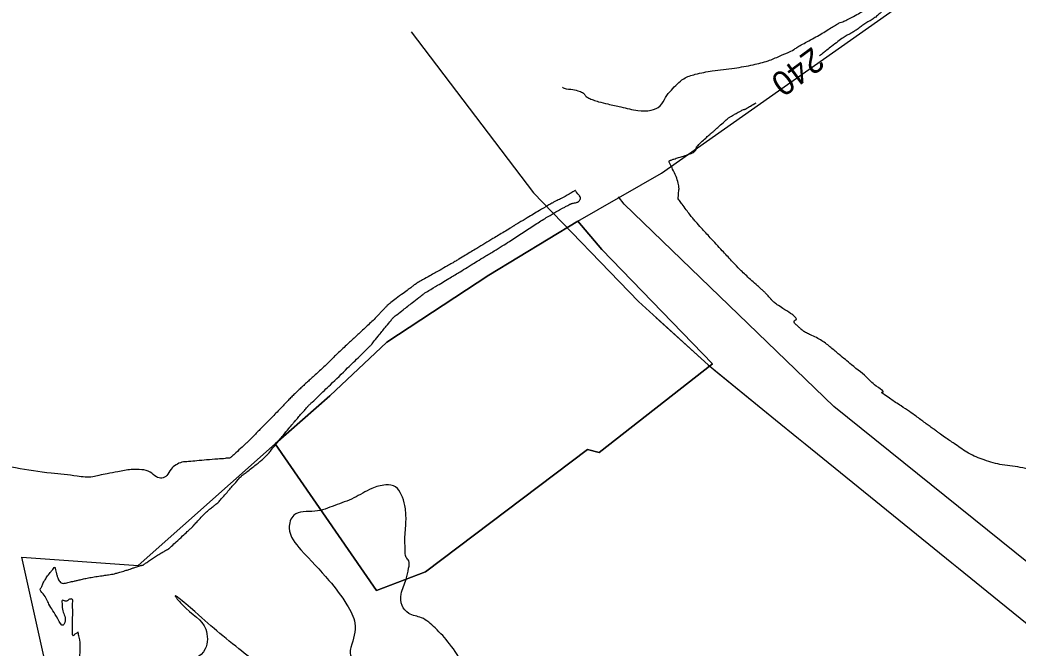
# Model space of a CAD drawing. Extents: x -478464 to -472469, y -1120963 to -1113785.
# Drawn here: x -477139.2 to -476975, y -1115096.3 to -1114993 of the extents above; entities that cross this region are included whole.
import ezdxf

# ---------------------------------------------------------------- set-up
doc = ezdxf.new("R2010")
doc.units = 0
for name, color, linetype in [('ObPÚ', 7, 'Continuous'), ('silnice', 7, 'Continuous'), ('telekomunikační kabel_O2', 7, 'Continuous'), ('Vrstevnice_hlavni', 7, 'Continuous'), ('Vrstevnice_popis', 7, 'Continuous'), ('Vrstevnice_vedlejsi', 7, 'Continuous')]:
    doc.layers.add(name, color=color, linetype=linetype)

msp = doc.modelspace()

# ---------------------------------------------------------------- linework, layer by layer
at = {"layer": 'ObPÚ'}
for p, q in [((-477047.46, -1115026.08), (-477062.09, -1115034.97)), ((-477043.48, -1115030.71), (-477047.46, -1115026.08)), ((-477072.47, -1115083.76), (-477045.85, -1115063.61))]:
    msp.add_line(p, q, dxfattribs=at)
for points in [[(-477231.42, -1115250.62), (-477154.22, -1115173.58), (-477134.18, -1115148.75), (-477133.16, -1115130.26), (-477132.09, -1115111.94), (-477138.91, -1115081.32), (-477119.74, -1115082.72), (-477097.23, -1115062.71), (-477080.55, -1115086.81), (-477072.47, -1115083.76), (-477045.85, -1115063.61), (-477043.93, -1115064.09), (-477025.31, -1115049.55), (-477043.48, -1115030.71), (-477047.46, -1115026.08), (-477033.7, -1115018.17), (-476933.96, -1114947.92), (-476834.35, -1114877.76), (-476714.64, -1114803.8), (-476602.93, -1114745.91), (-476491.34, -1114705.52)], [(-477047.46, -1115026.08), (-477043.48, -1115030.71), (-477025.31, -1115049.55), (-477043.93, -1115064.09), (-477045.85, -1115063.61), (-477072.47, -1115083.76), (-477080.55, -1115086.81), (-477097.23, -1115062.71), (-477088.23, -1115054.79), (-477078.85, -1115045.98), (-477062.09, -1115034.97), (-477047.46, -1115026.08)], [(-477045.85, -1115063.61), (-477043.93, -1115064.09), (-477025.31, -1115049.55), (-477043.48, -1115030.71)], [(-477062.09, -1115034.97), (-477078.85, -1115045.98), (-477088.23, -1115054.79), (-477097.23, -1115062.71), (-477080.55, -1115086.81), (-477072.47, -1115083.76)]]:
    msp.add_lwpolyline(points, dxfattribs=at)
at = {"layer": 'silnice'}
msp.add_lwpolyline([(-476200.543, -1116268.153), (-476239.965, -1116179.199), (-476260.934, -1116109.546), (-476288.613, -1116007.164), (-476289.451, -1115970.24), (-476274.354, -1115930.798), (-476261.922, -1115907.288), (-476366.595, -1115823.727), (-476390.845, -1115803.24), (-476425.665, -1115718.481), (-476494.983, -1115557.356), (-476524.795, -1115496.42), (-476580.823, -1115418.032), (-476641.911, -1115352.297), (-476741.891, -1115268.259), (-476824.194, -1115202.313), (-477005.33, -1115056.573), (-477039.82, -1115023.276), (-477040.729, -1115022.048)], dxfattribs=at)
at = {"layer": 'telekomunikační kabel_O2'}
for p, q in [((-477011.16, -1115061.79), (-477010.07, -1115062.67)), ((-477011.16, -1115061.79), (-477010.07, -1115062.67)), ((-476985.91, -1115082.25), (-476984.82, -1115083.13)), ((-476985.91, -1115082.25), (-476984.82, -1115083.13))]:
    msp.add_line(p, q, dxfattribs=at)
for points in [[(-477074.85, -1114994.92), (-477054.75, -1115021.38), (-477037.48, -1115039.27), (-477026.01, -1115049.69), (-477014.91, -1115058.73)], [(-477034.596, -1115041.89), (-477026.01, -1115049.69), (-477014.91, -1115058.73)], [(-477025.002, -1115050.511), (-477014.91, -1115058.73)], [(-477025.002, -1115050.511), (-477014.91, -1115058.73)], [(-477014.91, -1115058.73), (-477011.16, -1115061.79)], [(-477014.91, -1115058.73), (-477011.16, -1115061.79)], [(-477014.91, -1115058.73), (-477014.596, -1115058.986)], [(-477014.91, -1115058.73), (-477014.596, -1115058.986)], [(-477010.07, -1115062.67), (-476985.91, -1115082.25)], [(-476984.82, -1115083.13), (-476978.14, -1115088.55), (-476938.13, -1115120.98)]]:
    msp.add_lwpolyline(points, dxfattribs=at)
at = {"layer": 'Vrstevnice_hlavni'}
for points in [[(-477049.979, -1115004.029), (-477049.673, -1115004.193), (-477048.26, -1115004.404), (-477047.204, -1115004.683), (-477046.505, -1115005.027), (-477046.164, -1115005.438), (-477045.639, -1115005.805), (-477044.929, -1115006.127), (-477044.034, -1115006.405), (-477042.508, -1115006.787), (-477040.351, -1115007.273), (-477037.562, -1115007.863), (-477035.407, -1115007.799), (-477033.886, -1115007.079), (-477033, -1115005.704), (-477032.062, -1115004.503), (-477031.073, -1115003.477), (-477030.034, -1115002.625), (-477028.119, -1115001.907), (-477025.328, -1115001.324), (-477021.663, -1115000.876), (-477018.599, -1115000.325), (-477016.138, -1114999.672), (-477014.278, -1114998.917), (-477012.873, -1114998.304), (-477011.923, -1114997.835), (-477011.428, -1114997.509), (-477010.705, -1114997.08), (-477009.754, -1114996.549), (-477008.574, -1114995.914), (-477007.491, -1114995.299), (-477006.505, -1114994.702), (-477005.616, -1114994.125), (-477004.874, -1114993.69), (-477004.28, -1114993.398), (-477003.833, -1114993.249), (-477003.188, -1114992.955), (-477002.345, -1114992.516), (-477001.305, -1114991.933), (-477000.403, -1114991.481), (-476999.64, -1114991.162), (-476999.016, -1114990.973), (-476998.464, -1114990.728), (-476997.985, -1114990.425), (-476997.579, -1114990.066), (-476997.143, -1114989.765), (-476996.676, -1114989.524), (-476996.178, -1114989.342), (-476995.627, -1114989.011), (-476995.023, -1114988.533), (-476994.365, -1114987.907), (-476993.741, -1114987.384), (-476993.153, -1114986.963), (-476992.599, -1114986.645), (-476992.009, -1114986.355), (-476991.383, -1114986.092), (-476990.719, -1114985.856), (-476990.255, -1114985.689), (-476989.991, -1114985.591), (-476989.925, -1114985.561), (-476989.901, -1114985.553), (-476989.919, -1114985.568), (-476989.977, -1114985.605), (-476990.02, -1114985.633), (-476990.048, -1114985.653), (-476990.061, -1114985.663), (-476990.326, -1114985.857), (-476990.841, -1114986.233), (-476991.608, -1114986.792), (-476992.308, -1114987.388), (-476992.94, -1114988.02), (-476993.504, -1114988.689), (-476994.025, -1114989.245), (-476994.503, -1114989.688), (-476994.937, -1114990.017), (-476995.402, -1114990.301), (-476995.899, -1114990.54), (-476996.428, -1114990.734), (-476996.92, -1114991.026), (-476997.375, -1114991.417), (-476997.795, -1114991.906), (-476998.298, -1114992.365), (-476998.884, -1114992.793), (-476999.553, -1114993.19), (-477000.214, -1114993.61), (-477000.867, -1114994.052), (-477001.512, -1114994.518), (-477002.106, -1114994.907), (-477002.649, -1114995.22), (-477003.142, -1114995.458), (-477003.814, -1114995.885), (-477004.665, -1114996.502)], [(-477004.665, -1114996.502), (-477005.695, -1114997.309), (-477006.489, -1114997.933), (-477007.047, -1114998.372), (-477007.691, -1114998.882)], [(-477017.894, -1115036.673), (-477018.831, -1115035.848), (-477019.673, -1115035.079), (-477020.422, -1115034.367), (-477021.076, -1115033.712), (-477022.168, -1115032.564), (-477023.697, -1115030.923), (-477025.662, -1115028.788), (-477027.122, -1115027.188), (-477028.074, -1115026.123), (-477028.52, -1115025.593), (-477029.034, -1115024.943), (-477029.617, -1115024.173), (-477030.269, -1115023.282), (-477030.708, -1115022.682), (-477030.934, -1115022.374), (-477030.946, -1115022.357), (-477030.928, -1115022.077), (-477030.878, -1115021.535), (-477030.797, -1115020.729), (-477030.934, -1115019.788), (-477031.286, -1115018.713), (-477031.856, -1115017.503), (-477032.238, -1115016.683), (-477032.433, -1115016.253), (-477032.44, -1115016.214), (-477032.443, -1115016.185), (-477032.441, -1115016.166), (-477032.435, -1115016.159), (-477032.431, -1115016.153), (-477032.428, -1115016.149), (-477032.426, -1115016.147), (-477032.373, -1115016.122), (-477032.267, -1115016.074), (-477032.11, -1115016.003), (-477031.64, -1115015.843), (-477030.858, -1115015.596), (-477029.763, -1115015.26), (-477028.959, -1115014.975), (-477028.444, -1115014.74), (-477028.219, -1115014.556), (-477028.06, -1115014.364), (-477027.968, -1115014.165), (-477027.943, -1115013.958), (-477027.674, -1115013.593), (-477027.161, -1115013.071), (-477026.405, -1115012.392), (-477025.889, -1115011.927), (-477025.616, -1115011.677), (-477025.583, -1115011.642), (-477025.534, -1115011.602), (-477025.469, -1115011.556), (-477025.387, -1115011.505), (-477025.033, -1115011.201), (-477024.407, -1115010.643), (-477023.509, -1115009.833), (-477022.858, -1115009.263), (-477022.455, -1115008.935), (-477022.299, -1115008.848), (-477021.991, -1115008.674), (-477021.533, -1115008.413), (-477020.923, -1115008.064), (-477020.468, -1115007.826), (-477020.167, -1115007.697), (-477020.021, -1115007.678), (-477019.883, -1115007.635), (-477019.754, -1115007.567), (-477019.633, -1115007.475), (-477019.398, -1115007.325), (-477019.047, -1115007.117), (-477018.115, -1115006.584)], [(-476873.251, -1115143.677), (-476873.507, -1115142.01), (-476873.554, -1115139.102), (-476873.522, -1115134.12), (-476873.41, -1115127.063), (-476873.808, -1115122.086), (-476874.717, -1115119.19), (-476876.136, -1115118.374), (-476877.354, -1115117.171), (-476878.371, -1115115.579), (-476879.185, -1115113.6), (-476882.364, -1115111.475), (-476887.908, -1115109.205), (-476895.815, -1115106.789), (-476902.242, -1115103.761), (-476907.186, -1115100.12), (-476910.649, -1115095.867), (-476913.66, -1115091.883), (-476916.218, -1115088.167), (-476918.324, -1115084.72), (-476919.725, -1115082.379), (-476920.421, -1115081.145), (-476920.412, -1115081.017), (-476920.426, -1115080.932), (-476920.462, -1115080.891), (-476920.521, -1115080.893), (-476920.576, -1115080.895), (-476920.627, -1115080.896), (-476920.674, -1115080.898), (-476921.736, -1115080.799), (-476923.814, -1115080.599), (-476926.907, -1115080.3), (-476932.302, -1115079.591), (-476940, -1115078.472), (-476950, -1115076.944), (-476957.876, -1115075.006), (-476963.629, -1115072.657), (-476967.259, -1115069.897), (-476970.802, -1115067.892), (-476974.259, -1115066.643), (-476977.631, -1115066.149), (-476980.601, -1115065.341), (-476983.17, -1115064.218), (-476985.338, -1115062.781), (-476986.878, -1115061.747), (-476987.79, -1115061.118), (-476988.074, -1115060.892), (-476988.478, -1115060.587), (-476989.003, -1115060.204), (-476989.648, -1115059.743), (-476990.332, -1115059.246), (-476991.055, -1115058.714), (-476991.817, -1115058.146), (-476992.891, -1115057.395), (-476994.277, -1115056.46), (-476995.976, -1115055.343), (-476997.039, -1115054.593), (-476997.464, -1115054.21), (-476997.254, -1115054.195), (-476998.009, -1115053.437), (-476999.729, -1115051.937), (-477002.416, -1115049.693), (-477004.444, -1115048.001), (-477005.814, -1115046.86), (-477006.527, -1115046.27), (-477007.324, -1115045.723), (-477008.206, -1115045.221), (-477009.173, -1115044.763), (-477009.833, -1115044.445), (-477010.186, -1115044.267), (-477010.232, -1115044.228), (-477010.318, -1115044.158), (-477010.443, -1115044.058), (-477010.608, -1115043.927), (-477010.866, -1115043.703), (-477011.219, -1115043.389), (-477011.666, -1115042.982), (-477011.859, -1115042.654), (-477011.796, -1115042.405), (-477011.479, -1115042.235), (-477011.695, -1115041.846), (-477012.445, -1115041.236), (-477013.729, -1115040.407), (-477014.642, -1115039.799), (-477015.184, -1115039.41), (-477015.355, -1115039.241), (-477015.476, -1115039.117), (-477015.545, -1115039.038), (-477015.564, -1115039.003), (-477015.672, -1115038.875), (-477015.869, -1115038.653), (-477016.157, -1115038.339), (-477016.405, -1115038.07), (-477016.615, -1115037.849), (-477016.786, -1115037.674), (-477017.213, -1115037.282), (-477017.894, -1115036.673)]]:
    msp.add_spline(points, degree=3, dxfattribs=at)
at = {"layer": 'Vrstevnice_vedlejsi'}
for points in [[(-477108.024, -1115073.453), (-477107.41, -1115072.982), (-477106.961, -1115072.629), (-477106.676, -1115072.395), (-477106.556, -1115072.278), (-477106.091, -1115071.757), (-477105.281, -1115070.832), (-477104.126, -1115069.502), (-477103.309, -1115068.574), (-477102.828, -1115068.046), (-477102.685, -1115067.92), (-477102.316, -1115067.626), (-477101.72, -1115067.165), (-477100.898, -1115066.537), (-477100.184, -1115065.97), (-477099.579, -1115065.464), (-477099.081, -1115065.02), (-477098.73, -1115064.701), (-477098.524, -1115064.509), (-477098.465, -1115064.444), (-477098.01, -1115063.889), (-477097.162, -1115062.844), (-477095.919, -1115061.311), (-477094.978, -1115060.158), (-477094.339, -1115059.385), (-477094.002, -1115058.992), (-477093.57, -1115058.494), (-477093.044, -1115057.889), (-477092.423, -1115057.178), (-477091.967, -1115056.663), (-477091.675, -1115056.343), (-477091.547, -1115056.218), (-477091.414, -1115056.093), (-477091.276, -1115055.968), (-477091.133, -1115055.843), (-477090.09, -1115054.841), (-477088.145, -1115052.963), (-477085.299, -1115050.207), (-477083.328, -1115048.299), (-477082.232, -1115047.238), (-477082.012, -1115047.025), (-477081.803, -1115046.81), (-477081.606, -1115046.593), (-477081.422, -1115046.376), (-477080.916, -1115045.76), (-477080.09, -1115044.745), (-477078.942, -1115043.332), (-477078.165, -1115042.381), (-477077.759, -1115041.889), (-477077.722, -1115041.859), (-477077.193, -1115041.444), (-477076.171, -1115040.644), (-477074.656, -1115039.459), (-477073.586, -1115038.623), (-477072.96, -1115038.136), (-477072.779, -1115037.999), (-477071.961, -1115037.49), (-477070.508, -1115036.61), (-477068.419, -1115035.359), (-477066.799, -1115034.381), (-477065.649, -1115033.675), (-477064.968, -1115033.243), (-477064.004, -1115032.647), (-477062.756, -1115031.889), (-477061.226, -1115030.967), (-477059.874, -1115030.136), (-477058.7, -1115029.396), (-477057.706, -1115028.747), (-477056.705, -1115028.092), (-477055.698, -1115027.432), (-477054.685, -1115026.767), (-477053.73, -1115026.157), (-477052.836, -1115025.601), (-477052, -1115025.101), (-477051.326, -1115024.7), (-477050.814, -1115024.399), (-477050.463, -1115024.197), (-477050.058, -1115023.975), (-477049.6, -1115023.733), (-477049.089, -1115023.47), (-477048.739, -1115023.29), (-477048.551, -1115023.192), (-477048.525, -1115023.177), (-477048.392, -1115023.144), (-477048.151, -1115023.091), (-477047.802, -1115023.02), (-477047.557, -1115022.962), (-477047.416, -1115022.917), (-477047.38, -1115022.886), (-477047.304, -1115022.801), (-477047.188, -1115022.663), (-477047.034, -1115022.472), (-477047.024, -1115022.224), (-477047.159, -1115021.92), (-477047.44, -1115021.559), (-477047.642, -1115021.3), (-477047.764, -1115021.143)], [(-477047.764, -1115021.143), (-477047.807, -1115021.087), (-477047.84, -1115021.051), (-477047.862, -1115021.035), (-477047.874, -1115021.038), (-477048.066, -1115021.148), (-477048.439, -1115021.365), (-477048.993, -1115021.689), (-477049.369, -1115021.906), (-477049.566, -1115022.018), (-477049.585, -1115022.024), (-477049.603, -1115022.032), (-477049.62, -1115022.044), (-477049.636, -1115022.059), (-477049.869, -1115022.179), (-477050.319, -1115022.405), (-477050.986, -1115022.735), (-477051.44, -1115022.961), (-477051.68, -1115023.08), (-477051.707, -1115023.094), (-477052.394, -1115023.504), (-477053.742, -1115024.308), (-477055.751, -1115025.507), (-477057.143, -1115026.339), (-477057.916, -1115026.803), (-477058.072, -1115026.899), (-477058.233, -1115027.001), (-477058.398, -1115027.108), (-477058.569, -1115027.221), (-477059.569, -1115027.831), (-477061.399, -1115028.936), (-477064.059, -1115030.537), (-477065.922, -1115031.657), (-477066.987, -1115032.295), (-477067.255, -1115032.451), (-477067.533, -1115032.618), (-477067.822, -1115032.796), (-477068.122, -1115032.984), (-477068.88, -1115033.421), (-477070.096, -1115034.105), (-477071.77, -1115035.038), (-477072.989, -1115035.726), (-477073.751, -1115036.168), (-477074.057, -1115036.365), (-477074.333, -1115036.554), (-477074.579, -1115036.736), (-477074.794, -1115036.91), (-477075.324, -1115037.31), (-477076.168, -1115037.936), (-477077.327, -1115038.79), (-477078.203, -1115039.464), (-477078.798, -1115039.959), (-477079.111, -1115040.275), (-477079.455, -1115040.634), (-477079.831, -1115041.038), (-477080.238, -1115041.485), (-477080.787, -1115042.043), (-477081.476, -1115042.712), (-477082.307, -1115043.493), (-477083.019, -1115044.159), (-477083.61, -1115044.71), (-477084.082, -1115045.147), (-477084.651, -1115045.674), (-477085.315, -1115046.29), (-477086.075, -1115046.995), (-477086.782, -1115047.662), (-477087.437, -1115048.292), (-477088.038, -1115048.885), (-477088.682, -1115049.509), (-477089.369, -1115050.164), (-477090.097, -1115050.851), (-477090.791, -1115051.495), (-477091.451, -1115052.094), (-477092.076, -1115052.649), (-477092.683, -1115053.204), (-477093.273, -1115053.758), (-477093.846, -1115054.312), (-477094.405, -1115054.864), (-477094.949, -1115055.416), (-477095.479, -1115055.966), (-477096.073, -1115056.582), (-477096.731, -1115057.264), (-477097.453, -1115058.011), (-477098.084, -1115058.661), (-477098.627, -1115059.215), (-477099.079, -1115059.673), (-477099.591, -1115060.191), (-477100.163, -1115060.77), (-477100.794, -1115061.411), (-477101.243, -1115061.866), (-477101.509, -1115062.137), (-477101.593, -1115062.222), (-477101.981, -1115062.587), (-477102.673, -1115063.234), (-477103.67, -1115064.162), (-477104.352, -1115064.774), (-477104.719, -1115065.07)], [(-477104.719, -1115065.07), (-477104.772, -1115065.05), (-477105.421, -1115065.088), (-477106.667, -1115065.183), (-477108.511, -1115065.336), (-477110.106, -1115065.477), (-477111.454, -1115065.605), (-477112.553, -1115065.721), (-477113.519, -1115066.142), (-477114.351, -1115066.867), (-477115.049, -1115067.896), (-477115.853, -1115068.319), (-477116.761, -1115068.135), (-477117.775, -1115067.344), (-477119.166, -1115066.938), (-477120.933, -1115066.918), (-477123.077, -1115067.283), (-477124.834, -1115067.608), (-477126.206, -1115067.891), (-477127.191, -1115068.133), (-477129.805, -1115068.007), (-477134.047, -1115067.513), (-477139.917, -1115066.65), (-477145.027, -1115065.24), (-477149.376, -1115063.284), (-477151.42, -1115061.854)], [(-477084.767, -1115096.166), (-477084.101, -1115092.168), (-477085.414, -1115089.159), (-477088.375, -1115085.141), (-477092.982, -1115080.113), (-477094.907, -1115076.543), (-477094.15, -1115074.431), (-477090.711, -1115073.778), (-477087.427, -1115072.83), (-477084.299, -1115071.587), (-477081.325, -1115070.05), (-477079.03, -1115069.446), (-477077.412, -1115069.774), (-477076.472, -1115071.036), (-477075.902, -1115072.82), (-477075.702, -1115075.127), (-477075.871, -1115077.957), (-477075.854, -1115080.036), (-477075.649, -1115081.363), (-477075.256, -1115081.94), (-477075.268, -1115083.139), (-477075.685, -1115084.961), (-477076.505, -1115087.406), (-477076.358, -1115089.277), (-477075.242, -1115090.575), (-477073.158, -1115091.299), (-477070.923, -1115092.964), (-477068.536, -1115095.569), (-477065.998, -1115099.114), (-477064.928, -1115101.316), (-477065.326, -1115102.175), (-477067.193, -1115101.689), (-477068.694, -1115101.308), (-477069.828, -1115101.031), (-477070.596, -1115100.857), (-477072.409, -1115100.429), (-477075.269, -1115099.746), (-477079.173, -1115098.808), (-477081.829, -1115098.176), (-477083.236, -1115097.849), (-477083.394, -1115097.828), (-477083.654, -1115097.801), (-477084.015, -1115097.767), (-477084.479, -1115097.728), (-477084.768, -1115097.532), (-477084.883, -1115097.181), (-477084.767, -1115096.166)], [(-477129.643, -1115093.662), (-477129.855, -1115093.807), (-477130.059, -1115093.953), (-477130.255, -1115094.099), (-477130.445, -1115094.246), (-477130.55, -1115093.657), (-477130.571, -1115092.334), (-477130.508, -1115090.275), (-477130.534, -1115088.901), (-477130.65, -1115088.214), (-477130.857, -1115088.211), (-477131.052, -1115088.259), (-477131.235, -1115088.355), (-477131.407, -1115088.501), (-477131.624, -1115088.556), (-477131.885, -1115088.52), (-477132.189, -1115088.393), (-477132.278, -1115088.939), (-477132.151, -1115090.158), (-477131.807, -1115092.05), (-477132.073, -1115092.497), (-477132.948, -1115091.498), (-477134.433, -1115089.053), (-477135.392, -1115087.379), (-477135.824, -1115086.476), (-477135.732, -1115086.343), (-477135.622, -1115086.14), (-477135.496, -1115085.867), (-477135.352, -1115085.524), (-477135.069, -1115085.043), (-477134.645, -1115084.425), (-477134.081, -1115083.669), (-477133.693, -1115083.193), (-477133.481, -1115082.995), (-477133.446, -1115083.075), (-477133.419, -1115083.139), (-477133.4, -1115083.187), (-477133.39, -1115083.217), (-477133.336, -1115083.429), (-477133.239, -1115083.824), (-477133.098, -1115084.4), (-477132.937, -1115084.867), (-477132.754, -1115085.224), (-477132.55, -1115085.472), (-477132.273, -1115085.607), (-477131.924, -1115085.629), (-477131.503, -1115085.538), (-477131.093, -1115085.446), (-477130.693, -1115085.354), (-477130.303, -1115085.261), (-477129.783, -1115085.141), (-477129.131, -1115084.995), (-477128.35, -1115084.823), (-477127.47, -1115084.655), (-477126.491, -1115084.493), (-477125.414, -1115084.335), (-477124.621, -1115084.217), (-477124.114, -1115084.138), (-477123.891, -1115084.098), (-477123.449, -1115083.985), (-477122.787, -1115083.8), (-477121.905, -1115083.541), (-477121.265, -1115083.345), (-477120.867, -1115083.213), (-477120.711, -1115083.143), (-477120.481, -1115083.058), (-477120.176, -1115082.956), (-477119.798, -1115082.837), (-477119.534, -1115082.756), (-477119.385, -1115082.712), (-477119.35, -1115082.705), (-477119.288, -1115082.693), (-477119.198, -1115082.677), (-477119.082, -1115082.657), (-477119.001, -1115082.642), (-477118.957, -1115082.632), (-477118.949, -1115082.628), (-477118.741, -1115082.484), (-477118.333, -1115082.199), (-477117.725, -1115081.775), (-477117.071, -1115081.344), (-477116.374, -1115080.908), (-477115.631, -1115080.466), (-477115.101, -1115080.147), (-477114.783, -1115079.952), (-477114.678, -1115079.88), (-477114.253, -1115079.504), (-477113.508, -1115078.823), (-477112.443, -1115077.838), (-477111.674, -1115077.129), (-477111.202, -1115076.694), (-477111.026, -1115076.535), (-477110.663, -1115076.156), (-477110.113, -1115075.558), (-477109.375, -1115074.741), (-477108.679, -1115074.039), (-477108.024, -1115073.453)], [(-477145.994, -1115130.93), (-477145.907, -1115130.949), (-477145.792, -1115130.975), (-477145.65, -1115131.008), (-477145.481, -1115131.047), (-477145.355, -1115131.153), (-477145.271, -1115131.326), (-477145.229, -1115131.567), (-477145.169, -1115131.745), (-477145.091, -1115131.861), (-477144.995, -1115131.914), (-477144.768, -1115132.33), (-477144.41, -1115133.109), (-477143.921, -1115134.25), (-477143.473, -1115135.123), (-477143.067, -1115135.728), (-477142.703, -1115136.064), (-477142.298, -1115136.403), (-477141.851, -1115136.742), (-477141.362, -1115137.084), (-477140.677, -1115137.524), (-477139.796, -1115138.061), (-477138.718, -1115138.696), (-477137.989, -1115139.121), (-477137.608, -1115139.337), (-477137.576, -1115139.344), (-477137.371, -1115138.849), (-477136.992, -1115137.853), (-477136.441, -1115136.356), (-477135.916, -1115135.328), (-477135.418, -1115134.771), (-477134.946, -1115134.683), (-477134.587, -1115134.579), (-477134.341, -1115134.46), (-477134.209, -1115134.324), (-477133.319, -1115134.179), (-477131.672, -1115134.026), (-477129.269, -1115133.863), (-477128.244, -1115133.003), (-477128.597, -1115131.444), (-477130.328, -1115129.187), (-477130.863, -1115127.236), (-477130.202, -1115125.591), (-477128.344, -1115124.252), (-477126.5, -1115123.02), (-477124.668, -1115121.895), (-477122.85, -1115120.877), (-477121.643, -1115120.158), (-477121.049, -1115119.737), (-477121.066, -1115119.615), (-477121.462, -1115119.154), (-477122.237, -1115118.356), (-477123.39, -1115117.219), (-477124.078, -1115116.277), (-477124.301, -1115115.53), (-477124.06, -1115114.978), (-477124.281, -1115113.735), (-477124.966, -1115111.8), (-477126.113, -1115109.174), (-477123.549, -1115107.946), (-477117.274, -1115108.116), (-477107.287, -1115109.684), (-477100.243, -1115110.346), (-477096.142, -1115110.101), (-477094.985, -1115108.95), (-477094.099, -1115108.048), (-477093.486, -1115107.396), (-477093.145, -1115106.994), (-477092.79, -1115106.515), (-477092.422, -1115105.958), (-477092.04, -1115105.325), (-477091.701, -1115104.783), (-477091.403, -1115104.332), (-477091.147, -1115103.973), (-477091.418, -1115103.476), (-477092.215, -1115102.842), (-477093.538, -1115102.069), (-477094.274, -1115101.745), (-477094.421, -1115101.87), (-477093.98, -1115102.444), (-477094.699, -1115102.169), (-477096.577, -1115101.045), (-477099.615, -1115099.073), (-477103.181, -1115096.412), (-477107.275, -1115093.063), (-477111.897, -1115089.024), (-477113.665, -1115087.698), (-477112.579, -1115089.085), (-477108.64, -1115093.184), (-477108.708, -1115096.426), (-477112.784, -1115098.812), (-477120.869, -1115100.342), (-477126.312, -1115100.433), (-477129.113, -1115099.086), (-477129.272, -1115096.301), (-477129.449, -1115094.493), (-477129.643, -1115093.662)]]:
    msp.add_spline(points, degree=3, dxfattribs=at)

# ---------------------------------------------------------------- texts
at = {"layer": 'Vrstevnice_popis'}
msp.add_text(' 240 ', height=4, rotation=216.46088, dxfattribs=at).set_placement((-477007.655, -1114996.369))

doc.saveas('drawing.dxf')
